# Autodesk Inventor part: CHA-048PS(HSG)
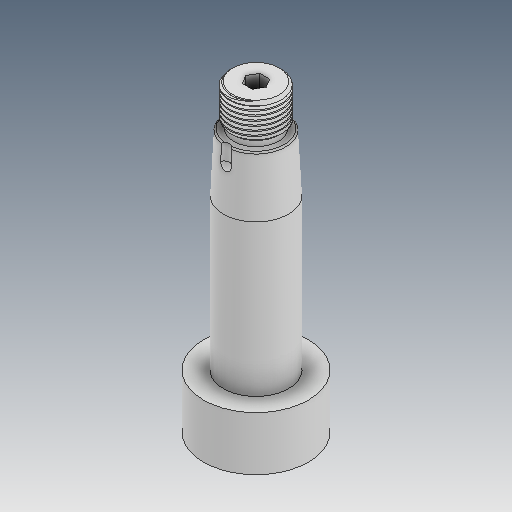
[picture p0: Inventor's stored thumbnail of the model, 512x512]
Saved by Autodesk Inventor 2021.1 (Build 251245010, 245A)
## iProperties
Created: 2021-05
Part Number: CHA-048PS(HSG)
Material: Ogólny
Document SubType Name: Modeling
Designer: user
Density: 1 g/cm^3
Appearance: Domyślna
Author: user
Revision Number: ÈÎºÎ
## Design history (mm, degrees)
feature "Ô²½Ç2"
node "Bryła1"
